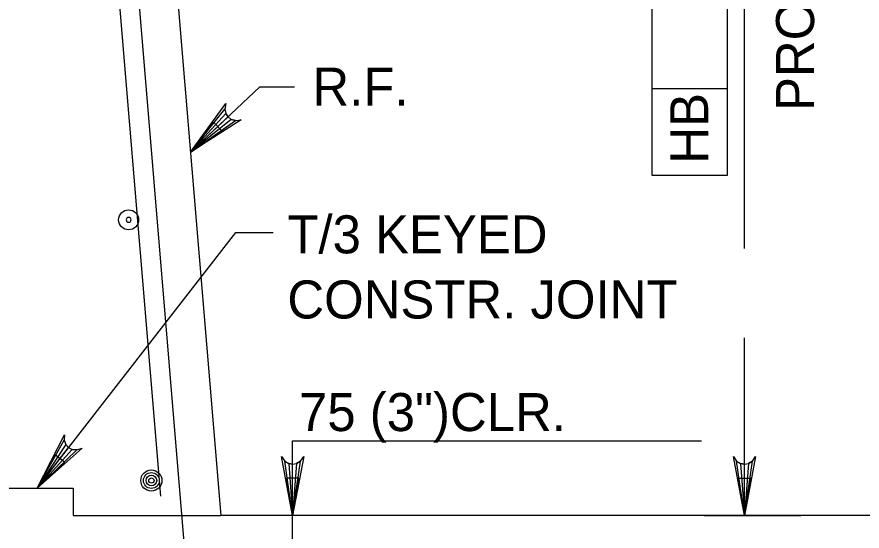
# Model space of a CAD drawing. Extents: x 634540 to 640306, y 296059 to 300275.
# Drawn here: x 639118.2 to 639184.8, y 298220.1 to 298260.6 of the extents above; entities that cross this region are included whole.
import ezdxf

# ---------------------------------------------------------------- set-up
doc = ezdxf.new("R2010")
doc.units = 0
for name, color, linetype in [('3', 7, 'Continuous'), ('4', 7, 'Continuous'), ('5', 7, 'Continuous'), ('6', 7, 'Continuous'), ('7', 7, 'Continuous'), ('9', 7, 'Continuous')]:
    doc.layers.add(name, color=color, linetype=linetype)

# ---------------------------------------------------------------- blocks, each defined once
blk = doc.blocks.new('B')
at = {"layer": '3'}
blk.add_circle((0, 0), 0.16, dxfattribs=at)
for start, end in [(0, 180), (180, 0)]:
    blk.add_arc((0, 0), 0.0391, start, end, dxfattribs=at)

msp = doc.modelspace()

# ---------------------------------------------------------------- linework, layer by layer
at = {"layer": '3'}
for p, q in [((639175.574, 298242.383), (639175.574, 298292.027)), ((639168.291, 298254.971), (639168.291, 298283.426)), ((639174.196, 298283.426), (639174.196, 298248.125)), ((639131.894, 298249.96), (639137.361, 298255.121)), ((639137.361, 298255.121), (639140.094, 298255.121)), ((639168.291, 298248.125), (639168.291, 298254.971)), ((639174.196, 298254.971), (639168.291, 298254.971)), ((639174.196, 298248.125), (639168.291, 298248.125)), ((639119.789, 298223.474), (639135.461, 298243.629)), ((639135.461, 298243.629), (639138.413, 298243.629)), ((639175.574, 298221.312), (639175.574, 298235.335)), ((639139.944, 298227.209), (639172.193, 298227.209)), ((639172.4, 298221.311), (639180.002, 298221.311))]:
    msp.add_line(p, q, dxfattribs=at)
for points in [[(639131.894, 298249.96), (639134.683, 298253.796), (639134.592, 298253.367), (639134.673, 298253.013), (639134.848, 298252.75), (639135.102, 298252.558), (639135.45, 298252.458), (639135.883, 298252.525), (639131.894, 298249.96), (639135.45, 298252.458), (639135.102, 298252.558), (639131.894, 298249.96), (639134.848, 298252.75), (639134.673, 298253.013), (639131.894, 298249.96), (639134.592, 298253.367)], [(639119.789, 298223.474), (639121.96, 298227.688), (639121.935, 298227.253), (639122.068, 298226.916), (639122.283, 298226.68), (639122.562, 298226.532), (639122.922, 298226.486), (639123.339, 298226.618), (639119.789, 298223.474), (639122.922, 298226.486), (639122.562, 298226.532), (639119.789, 298223.474), (639122.283, 298226.68), (639122.068, 298226.916), (639119.789, 298223.474), (639121.935, 298227.253)], [(639139.944, 298221.303), (639139.071, 298225.963), (639139.319, 298225.605), (639139.632, 298225.42), (639139.944, 298225.365), (639140.257, 298225.42), (639140.569, 298225.605), (639140.817, 298225.963), (639139.944, 298221.303), (639140.569, 298225.605), (639140.257, 298225.42), (639139.944, 298221.303), (639139.944, 298225.365), (639139.632, 298225.42), (639139.944, 298221.303), (639139.319, 298225.605)], [(639175.573, 298221.311), (639174.7, 298225.972), (639174.948, 298225.613), (639175.26, 298225.428), (639175.573, 298225.374), (639175.885, 298225.428), (639176.198, 298225.613), (639176.446, 298225.972), (639175.573, 298221.311), (639176.198, 298225.613), (639175.885, 298225.428), (639175.573, 298221.311), (639175.573, 298225.374), (639175.26, 298225.428), (639175.573, 298221.311), (639174.948, 298225.613)]]:
    msp.add_lwpolyline(points, dxfattribs=at)
for points in [[(639134.379, 298251.627), (639133.702, 298252.344), (639131.894, 298249.958)], [(639121.989, 298225.503), (639121.212, 298226.107), (639119.789, 298223.474)], [(639175.081, 298224.263), (639176.064, 298224.263), (639175.573, 298221.311)]]:
    msp.add_lwpolyline(points, close=True, dxfattribs=at)
at = {"layer": '4'}
msp.add_line((639139.944, 298218.236), (639139.944, 298227.209), dxfattribs=at)
msp.add_lwpolyline([(639140.436, 298224.257), (639139.452, 298224.257), (639139.944, 298221.303)], close=True, dxfattribs=at)
at = {"layer": '5'}
for p, q in [((639127.487, 298265.799), (639132.646, 298203.906)), ((639125.973, 298265.457), (639129.523, 298222.849))]:
    msp.add_line(p, q, dxfattribs=at)
for radius in [0.833, 0.625, 0.417, 0.208]:
    msp.add_circle((639128.807, 298224.073), radius, dxfattribs=at)
at = {"layer": '6'}
msp.add_lwpolyline([(639104.407, 298221.311), (639115.439, 298221.311), (639115.439, 298223.474), (639122.631, 298223.474), (639122.631, 298221.311), (639134.281, 298221.311)], dxfattribs=at)
at = {"layer": '7'}
msp.add_line((639183.931, 298221.303), (639183.931, 298221.303), dxfattribs=at)
at = {"layer": '9'}
for p in [(639122.862, 298358.334), (639187.927, 298221.311)]:
    msp.add_line(p, (639134.281, 298221.311), dxfattribs=at)

# ---------------------------------------------------------------- block references
at = {"layer": '3', "xscale": 4.921475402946, "yscale": 4.921475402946, "rotation": 90}
msp.add_blockref('B', (639127.012, 298244.631), dxfattribs=at)

# ---------------------------------------------------------------- texts
at = {"layer": '3'}
for s, p in [('PROJECTION', (639181.058, 298253.217)), ('HB', (639172.712, 298249.062))]:
    msp.add_text(s, height=3.0001, rotation=90, dxfattribs=at).set_placement(p)
for s, height, p in [('R.F.', 3.0001, (639141.505, 298253.633)), ('T/3 KEYED', 3.0001, (639139.527, 298241.989)), ('CONSTR. JOINT', 3.00014, (639139.527, 298236.853)), ('75 (3")CLR.', 3.00014, (639140.446, 298227.972))]:
    msp.add_text(s, height=height, dxfattribs=at).set_placement(p)

doc.saveas('drawing.dxf')
